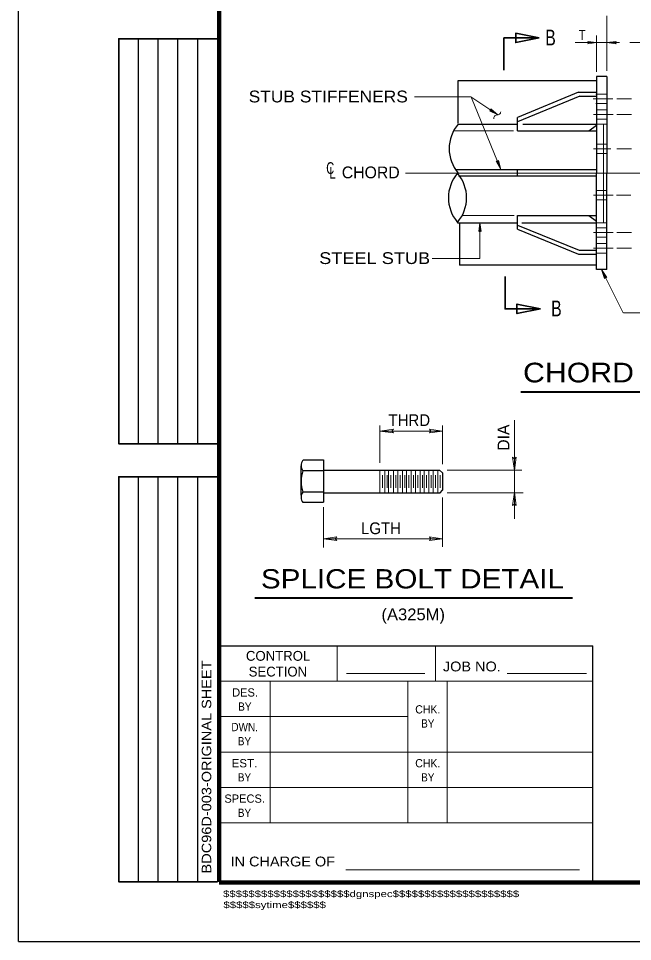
# Model space of a CAD drawing. Extents: x 312601.858 to 312602.699, y 144420.109 to 144420.704.
# Drawn here: x 312601.8578 to 312602.0139, y 144420.1095 to 144420.3443 of the extents above; entities that cross this region are included whole.
import ezdxf
from ezdxf.enums import TextEntityAlignment as Align

# ---------------------------------------------------------------- set-up
doc = ezdxf.new("R2010")
doc.units = 0
doc.header["$LTSCALE"] = 0.0012
doc.linetypes.add('DOT_DASHED', pattern=[7.7, 5, -1.2, 0.3, -1.2])
doc.linetypes.add('LONG_DASHED', pattern=[7.5, 6, -1.5])
for name, color, linetype, lineweight in [('1', 7, 'Continuous', 13), ('2', 7, 'Continuous', 25), ('39', 7, 'Continuous', 13), ('60', 7, 'Continuous', 25)]:
    doc.layers.add(name, color=color, linetype=linetype, lineweight=lineweight)

msp = doc.modelspace()

# ---------------------------------------------------------------- hatches: boundary and pattern name
at = {"layer": '39'}
for points in [[(312601.9779, 144420.3209), (312601.9779, 144420.3213), (312601.9797, 144420.3197), (312601.9775, 144420.3208)], [(312601.9795, 144420.3079), (312601.9798, 144420.3081), (312601.9804, 144420.3058), (312601.9792, 144420.308)], [(312602.007, 144420.2785), (312602.0068, 144420.2781), (312602.006, 144420.2804), (312602.0074, 144420.2784)]]:
    msp.add_hatch(color=256, dxfattribs=at).paths.add_polyline_path(points)

# ---------------------------------------------------------------- linework, layer by layer
at = {"layer": '1'}
for p, q in [((312602.0074, 144420.3449), (312602.0074, 144420.3309)), ((312602.0047, 144420.3399), (312602.0047, 144420.3307)), ((312601.973, 144420.3241), (312601.9803, 144420.306)), ((312602.0074, 144420.3174), (312602.0047, 144420.3174)), ((312602.0074, 144420.2923), (312602.0047, 144420.2923)), ((312601.9497, 144420.2407), (312601.9497, 144420.2312)), ((312601.9656, 144420.2407), (312601.9656, 144420.2309)), ((312601.9497, 144420.2393), (312601.9656, 144420.2393)), ((312601.9497, 144420.2294), (312601.9497, 144420.2236)), ((312601.9497, 144420.2291), (312601.9497, 144420.2237)), ((312601.9503, 144420.2249), (312601.9503, 144420.2281)), ((312601.9509, 144420.2294), (312601.9509, 144420.2236)), ((312601.9515, 144420.2249), (312601.9515, 144420.2281)), ((312601.9519, 144420.2294), (312601.9519, 144420.2236)), ((312601.9525, 144420.2249), (312601.9525, 144420.2281)), ((312601.9531, 144420.2294), (312601.9531, 144420.2236)), ((312601.9537, 144420.2249), (312601.9537, 144420.2281)), ((312601.9542, 144420.2294), (312601.9542, 144420.2236)), ((312601.9548, 144420.2249), (312601.9548, 144420.2281)), ((312601.9554, 144420.2294), (312601.9554, 144420.2236)), ((312601.956, 144420.2249), (312601.956, 144420.2281)), ((312601.9564, 144420.2294), (312601.9564, 144420.2236)), ((312601.957, 144420.2249), (312601.957, 144420.2281)), ((312601.9576, 144420.2294), (312601.9576, 144420.2236)), ((312601.9582, 144420.2249), (312601.9582, 144420.2281)), ((312601.9587, 144420.2294), (312601.9587, 144420.2236)), ((312601.9593, 144420.2249), (312601.9593, 144420.2281)), ((312601.9599, 144420.2294), (312601.9599, 144420.2236)), ((312601.9605, 144420.2249), (312601.9605, 144420.2281)), ((312601.9609, 144420.2294), (312601.9609, 144420.2236)), ((312601.9615, 144420.2249), (312601.9615, 144420.2281)), ((312601.9621, 144420.2294), (312601.9621, 144420.2236)), ((312601.9627, 144420.2249), (312601.9627, 144420.2281)), ((312601.9632, 144420.2294), (312601.9632, 144420.2236)), ((312601.9638, 144420.2249), (312601.9638, 144420.2281)), ((312601.9644, 144420.2294), (312601.9644, 144420.2236)), ((312601.965, 144420.2249), (312601.965, 144420.2281)), ((312601.9668, 144420.2294), (312601.9858, 144420.2294)), ((312601.9668, 144420.2236), (312601.9861, 144420.2236)), ((312601.9315, 144420.2212), (312601.9326, 144420.2212)), ((312601.9656, 144420.2224), (312601.9656, 144420.2099)), ((312601.9353, 144420.22), (312601.9353, 144420.2097)), ((312601.9353, 144420.2119), (312601.9656, 144420.2119))]:
    msp.add_line(p, q, dxfattribs=at)
at = {"layer": '1', "lineweight": 25}
for p, q in [((312602.0074, 144420.3295), (312602.0047, 144420.3295)), ((312602.0047, 144420.3295), (312602.0047, 144420.3049)), ((312602.0074, 144420.3295), (312602.0074, 144420.3049)), ((312601.9694, 144420.3174), (312601.9847, 144420.3174)), ((312602.0028, 144420.3157), (312602.0047, 144420.3171)), ((312602.0047, 144420.2804), (312602.0047, 144420.3049)), ((312602.0074, 144420.2804), (312602.0074, 144420.3049)), ((312602.0028, 144420.2941), (312602.0047, 144420.2927)), ((312601.9694, 144420.2923), (312601.9847, 144420.2923)), ((312602.0074, 144420.2804), (312602.0047, 144420.2804)), ((312601.9296, 144420.2305), (312601.9296, 144420.223)), ((312601.9302, 144420.232), (312601.9353, 144420.232)), ((312601.9353, 144420.232), (312601.9353, 144420.2212)), ((312601.9302, 144420.2293), (312601.9353, 144420.2293)), ((312601.9353, 144420.2294), (312601.9648, 144420.2294)), ((312601.9353, 144420.2293), (312601.9353, 144420.2237)), ((312601.9648, 144420.2294), (312601.9656, 144420.2287)), ((312601.9656, 144420.2287), (312601.9656, 144420.2243)), ((312601.9302, 144420.2239), (312601.9353, 144420.2239)), ((312601.9353, 144420.2236), (312601.965, 144420.2236)), ((312601.965, 144420.2236), (312601.9656, 144420.2243)), ((312601.9302, 144420.2212), (312601.9353, 144420.2212)), ((312601.9317, 144420.2212), (312601.9353, 144420.2212))]:
    msp.add_line(p, q, dxfattribs=at)
at = {"layer": '1', "linetype": 'LONG_DASHED'}
for p, q in [((312602.0073, 144420.325), (312602.0046, 144420.325)), ((312602.0073, 144420.3226), (312602.0046, 144420.3226)), ((312602.0074, 144420.321), (312602.0047, 144420.321)), ((312602.0074, 144420.3186), (312602.0047, 144420.3186)), ((312602.0065, 144420.3174), (312602.0065, 144420.3049)), ((312601.9684, 144420.3157), (312601.9836, 144420.3157)), ((312602.0074, 144420.3123), (312602.0047, 144420.3123)), ((312602.0074, 144420.3099), (312602.0047, 144420.3099)), ((312602.0065, 144420.2923), (312602.0065, 144420.3049)), ((312602.0074, 144420.3005), (312602.0047, 144420.3005)), ((312602.0074, 144420.2981), (312602.0047, 144420.2981)), ((312601.9706, 144420.2941), (312601.9838, 144420.2941)), ((312602.0074, 144420.291), (312602.0047, 144420.291)), ((312602.0074, 144420.2886), (312602.0047, 144420.2886)), ((312602.0074, 144420.287), (312602.0047, 144420.287)), ((312602.0074, 144420.2846), (312602.0047, 144420.2846))]:
    msp.add_line(p, q, dxfattribs=at)
at = {"layer": '1', "linetype": 'DOT_DASHED'}
for p, q in [((312602.0039, 144420.3238), (312602.0089, 144420.3238)), ((312602.0099, 144420.3238), (312602.0136, 144420.3238)), ((312602.004, 144420.3198), (312602.009, 144420.3198)), ((312602.0099, 144420.3198), (312602.0136, 144420.3198)), ((312602.004, 144420.3111), (312602.0084, 144420.3111)), ((312602.0099, 144420.3111), (312602.0136, 144420.3111)), ((312601.9562, 144420.3049), (312602.0586, 144420.3049)), ((312602.004, 144420.2993), (312602.009, 144420.2993)), ((312602.0098, 144420.2993), (312602.0135, 144420.2993)), ((312602.004, 144420.2898), (312602.009, 144420.2898)), ((312602.0099, 144420.2898), (312602.0136, 144420.2898)), ((312602.004, 144420.2858), (312602.009, 144420.2858)), ((312602.0099, 144420.2858), (312602.0136, 144420.2858))]:
    msp.add_line(p, q, dxfattribs=at)
at = {"layer": '1', "linetype": 'LONG_DASHED', "lineweight": 25}
for p, q in [((312601.986, 144420.3174), (312602.0047, 144420.3174)), ((312601.9858, 144420.2923), (312602.0047, 144420.2923))]:
    msp.add_line(p, q, dxfattribs=at)
at = {"layer": '1', "lineweight": 40}
for p, q in [((312601.9855, 144420.2493), (312602.1479, 144420.2493)), ((312601.9179, 144420.1969), (312601.9986, 144420.1969))]:
    msp.add_line(p, q, dxfattribs=at)
at = {"layer": '1'}
for points in [[(312601.9993, 144420.3381), (312602.0047, 144420.3381), (312602.0074, 144420.3381), (312602.0106, 144420.3381)], [(312602.0132, 144420.3381), (312602.0164, 144420.3381), (312602.0191, 144420.3381), (312602.0247, 144420.3381)], [(312601.9585, 144420.3243), (312601.9728, 144420.3243), (312601.9797, 144420.3197)], [(312601.9751, 144420.2923), (312601.9751, 144420.2832), (312601.963, 144420.2832)], [(312601.9839, 144420.2421), (312601.9839, 144420.2293), (312601.9839, 144420.2237), (312601.9839, 144420.217)]]:
    msp.add_lwpolyline(points, dxfattribs=at)
for points in [[(312602.0025, 144420.3384), (312602.0047, 144420.3381), (312602.0025, 144420.3378), (312602.0027, 144420.3381)], [(312602.0097, 144420.3378), (312602.0074, 144420.3381), (312602.0097, 144420.3384), (312602.0094, 144420.3381)], [(312601.9748, 144420.2901), (312601.9751, 144420.2923), (312601.9754, 144420.2901), (312601.9751, 144420.2903)], [(312601.9531, 144420.2389), (312601.9497, 144420.2393), (312601.9531, 144420.2398), (312601.9527, 144420.2393)], [(312601.9623, 144420.2398), (312601.9656, 144420.2393), (312601.9623, 144420.2389), (312601.9626, 144420.2393)], [(312601.9843, 144420.2327), (312601.9839, 144420.2293), (312601.9834, 144420.2327), (312601.9839, 144420.2323)], [(312601.9834, 144420.2204), (312601.9839, 144420.2237), (312601.9843, 144420.2204), (312601.9839, 144420.2207)], [(312601.9387, 144420.2115), (312601.9353, 144420.2119), (312601.9387, 144420.2124), (312601.9383, 144420.2119)], [(312601.9623, 144420.2124), (312601.9656, 144420.2119), (312601.9623, 144420.2115), (312601.9626, 144420.2119)]]:
    msp.add_lwpolyline(points, close=True, dxfattribs=at)
for centre, start, end in [((312601.979458, 144420.318833), 93.85064, 188.82974), ((312601.979533, 144420.320558), 261.17025, 356.14936)]:
    msp.add_arc(centre, 0.0008686, start, end, dxfattribs=at)
at = {"layer": '1', "lineweight": 25}
for centre, radius, start, end in [((312601.932025, 144420.230563), 0.0023838, 145.50634, 214.49366), ((312601.937988, 144420.226513), 0.008325, 161.07536, 198.92464), ((312601.932025, 144420.222463), 0.0023838, 145.50634, 214.49366)]:
    msp.add_arc(centre, radius, start, end, dxfattribs=at)
at = {"layer": '2'}
for p, q in [((312602.0002, 144420.3255), (312601.9847, 144420.3191)), ((312602.0005, 144420.3245), (312601.9847, 144420.318)), ((312602.0002, 144420.3255), (312602.0047, 144420.3255)), ((312602.0005, 144420.3245), (312602.0047, 144420.3245)), ((312601.9847, 144420.3157), (312601.9847, 144420.3191)), ((312601.9847, 144420.3157), (312602.0047, 144420.3157)), ((312601.9689, 144420.3058), (312602.0047, 144420.3058)), ((312601.9847, 144420.3042), (312601.9847, 144420.3058)), ((312601.9697, 144420.3042), (312602.0047, 144420.3042)), ((312601.9847, 144420.2941), (312602.0047, 144420.2941)), ((312601.9847, 144420.2907), (312601.9847, 144420.2941)), ((312601.9699, 144420.2921), (312601.9699, 144420.2815)), ((312601.9847, 144420.2917), (312602.0003, 144420.2853)), ((312601.9847, 144420.2907), (312602.0002, 144420.2843)), ((312602.0002, 144420.2843), (312602.0047, 144420.2843)), ((312602.0003, 144420.2853), (312602.0047, 144420.2853)), ((312602.0046, 144420.2815), (312601.9699, 144420.2815))]:
    msp.add_line(p, q, dxfattribs=at)
at = {"layer": '2', "lineweight": 13}
for p, q in [((312602.006, 144420.2804), (312602.0115, 144420.2694)), ((312602.0116, 144420.2694), (312602.0326, 144420.2694))]:
    msp.add_line(p, q, dxfattribs=at)
at = {"layer": '2'}
msp.add_lwpolyline([(312602.0047, 144420.3284), (312601.9695, 144420.3284), (312601.9695, 144420.3176)], dxfattribs=at)
for centre, radius, start, end in [((312601.976915, 144420.31115), 0.0096216, 139.48997, 220.51003), ((312601.976737, 144420.29865), 0.0096381, 139.57392, 220.42608), ((312601.962124, 144420.29865), 0.0095919, 319.33814, 40.66186)]:
    msp.add_arc(centre, radius, start, end, dxfattribs=at)
at = {"layer": '39', "lineweight": 25}
for p, q in [((312601.8578, 144420.1095), (312601.8578, 144420.7035)), ((312601.9088, 144420.1847), (312602.0038, 144420.1847)), ((312602.0038, 144420.1247), (312602.0038, 144420.1847)), ((312601.8578, 144420.1095), (312602.6988, 144420.1095))]:
    msp.add_line(p, q, dxfattribs=at)
at = {"layer": '39', "lineweight": 158}
for p, q in [((312601.9088, 144420.1247), (312601.9088, 144420.6645)), ((312601.9088, 144420.1245), (312602.6838, 144420.1245))]:
    msp.add_line(p, q, dxfattribs=at)
at = {"layer": '39'}
for p, q in [((312601.9088, 144420.1247), (312601.9088, 144420.1847)), ((312601.9388, 144420.1757), (312601.9388, 144420.1847)), ((312601.9638, 144420.1757), (312601.9638, 144420.1847)), ((312601.9412, 144420.1777), (312601.9611, 144420.1777)), ((312601.982, 144420.1777), (312602.0022, 144420.1777)), ((312601.9088, 144420.1757), (312602.0038, 144420.1757)), ((312601.9218, 144420.1397), (312601.9218, 144420.1757)), ((312601.9568, 144420.1397), (312601.9568, 144420.1757)), ((312601.9668, 144420.1397), (312601.9668, 144420.1757)), ((312601.9088, 144420.1667), (312601.9568, 144420.1667)), ((312601.9088, 144420.1577), (312602.0038, 144420.1577)), ((312601.9088, 144420.1487), (312602.0038, 144420.1487)), ((312601.9088, 144420.1397), (312602.0038, 144420.1397)), ((312601.941, 144420.1277), (312602.0004, 144420.1277)), ((312601.9088, 144420.1247), (312602.0038, 144420.1247))]:
    msp.add_line(p, q, dxfattribs=at)
at = {"layer": '39', "lineweight": 35}
for points in [[(312601.9902, 144420.3393), (312601.9842, 144420.3405), (312601.9842, 144420.3381)], [(312601.9905, 144420.2704), (312601.9845, 144420.2692), (312601.9845, 144420.2716)]]:
    msp.add_lwpolyline(points, close=True, dxfattribs=at)
at = {"layer": '39'}
for points in [[(312601.9842, 144420.3381), (312601.9902, 144420.3393), (312601.9842, 144420.3405)], [(312601.9779, 144420.3209), (312601.9779, 144420.3213), (312601.9797, 144420.3197), (312601.9775, 144420.3208)], [(312601.9795, 144420.3079), (312601.9798, 144420.3081), (312601.9804, 144420.3058), (312601.9792, 144420.308)], [(312602.007, 144420.2785), (312602.0068, 144420.2781), (312602.006, 144420.2804), (312602.0074, 144420.2784)], [(312601.9845, 144420.2716), (312601.9905, 144420.2704), (312601.9845, 144420.2692)]]:
    msp.add_lwpolyline(points, close=True, dxfattribs=at)
at = {"layer": '39', "lineweight": 35}
for points in [[(312601.9899, 144420.3393), (312601.9812, 144420.3393), (312601.9812, 144420.3311)], [(312601.9902, 144420.2704), (312601.9815, 144420.2704), (312601.9815, 144420.2786)]]:
    msp.add_lwpolyline(points, dxfattribs=at)
at = {"layer": '60'}
for p, q in [((312601.8883, 144420.2361), (312601.8883, 144420.3391)), ((312601.8933, 144420.2361), (312601.8933, 144420.3391)), ((312601.8983, 144420.2361), (312601.8983, 144420.3391)), ((312601.9034, 144420.2361), (312601.9034, 144420.3391)), ((312601.8883, 144420.1247), (312601.8883, 144420.2277)), ((312601.8933, 144420.1247), (312601.8933, 144420.2277)), ((312601.8983, 144420.1247), (312601.8983, 144420.2277)), ((312601.9034, 144420.1247), (312601.9034, 144420.2277))]:
    msp.add_line(p, q, dxfattribs=at)
at = {"layer": '60', "lineweight": 35}
for points in [[(312601.9084, 144420.2361), (312601.8833, 144420.2361), (312601.8833, 144420.3391), (312601.9084, 144420.3391)], [(312601.9084, 144420.1247), (312601.8833, 144420.1247), (312601.8833, 144420.2277), (312601.9084, 144420.2277)]]:
    msp.add_lwpolyline(points, dxfattribs=at)

# ---------------------------------------------------------------- texts
at = {"layer": '1'}
for s, height, p in [('CONTROL', 0.0025, (312601.9238, 144420.1809)), ('SECTION', 0.0025, (312601.92375, 144420.1769)), ('DES.', 0.0021, (312601.9154, 144420.1718)), ('SPECS.', 0.0021, (312601.9153, 144420.1448))]:
    msp.add_text(s, height=height, dxfattribs=at).set_placement(p, align=Align.CENTER)
for s, height, width, p in [('JOB NO.', 0.0025, 1.1, (312601.97305, 144420.1782)), ('BY', 0.0021, 0.9, (312601.91535, 144420.1682)), ('CHK.', 0.0021, 0.95, (312601.96185, 144420.1675)), ('DWN.', 0.0021, 0.9, (312601.9153, 144420.163)), ('BY', 0.0021, 0.9, (312601.96185, 144420.1639)), ('BY', 0.0021, 0.9, (312601.91525, 144420.1594)), ('EST.', 0.0021, 1.05, (312601.91525, 144420.1538)), ('CHK.', 0.0021, 0.95, (312601.96185, 144420.1538)), ('BY', 0.0021, 0.9, (312601.91525, 144420.1502)), ('BY', 0.0021, 0.9, (312601.96185, 144420.1502)), ('BY', 0.0021, 0.9, (312601.91525, 144420.1412)), ('IN CHARGE OF', 0.0025, 1.1, (312601.925, 144420.1286))]:
    msp.add_text(s, height=height, dxfattribs=dict(at, width=width)).set_placement(p, align=Align.CENTER)
at = {"layer": '2'}
for s, height, width, p in [('B', 0.004, 0.75, (312601.99305, 144420.3374)), ('T', 0.00255, 0.8, (312602.0011, 144420.3388)), ('STUB STIFFENERS', 0.003, 1.1, (312601.93655, 144420.3229)), ('C', 0.003, 0.7, (312601.93705, 144420.3047)), ('L', 0.003, 0.75, (312601.93765, 144420.3035)), ('STEEL STUB', 0.003, 1.15, (312601.94835, 144420.2818)), ('B', 0.004, 0.75, (312601.99455, 144420.2685)), ('CHORD SPLICE ASSEMBLY - TWELVE-BOLT', 0.005, 1.15, (312602.06725, 144420.2517)), ('THRD', 0.003, 0.95, (312601.95715, 144420.2406)), ('LGTH', 0.003, 0.95, (312601.94995, 144420.2131)), ('SPLICE BOLT DETAIL', 0.0049, 1.15, (312601.95795, 144420.1993)), ('(A325M)', 0.003, 1.05, (312601.95815, 144420.1912))]:
    msp.add_text(s, height=height, dxfattribs=dict(at, width=width)).set_placement(p, align=Align.CENTER)
msp.add_text('CHORD', height=0.003, dxfattribs=at).set_placement((312601.94735, 144420.3036), align=Align.CENTER)
msp.add_text('DIA', height=0.003, rotation=90, dxfattribs=at).set_placement((312601.9826, 144420.23765), align=Align.CENTER)
at = {"layer": '2', "width": 1.15}
msp.add_text('BDC96D-003-ORIGINAL SHEET', height=0.0024, rotation=90, dxfattribs=at).set_placement((312601.9068, 144420.1539), align=Align.CENTER)
at = {"layer": '2', "width": 1.3}
for s, p in [('$$$$$$$$$$$$$$$$$$$$dgnspec$$$$$$$$$$$$$$$$$$$$', (312601.9098, 144420.1208)), ('$$$$$sytime$$$$$$', (312601.9099, 144420.118))]:
    msp.add_text(s, height=0.001664, dxfattribs=at).set_placement(p)

doc.saveas('drawing.dxf')
